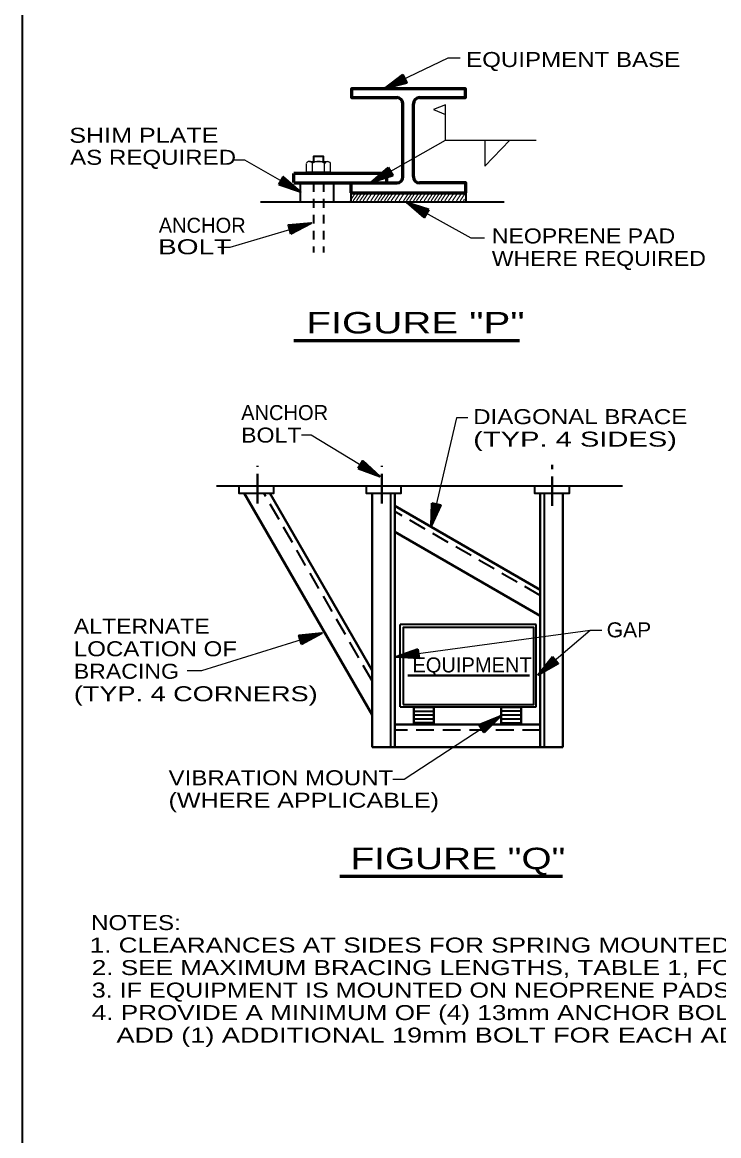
# Model space of a CAD drawing. Extents: x 55 to 190, y 198 to 264.
# Drawn here: x 102.59 to 114.38, y 231.1 to 249.95 of the extents above; entities that cross this region are included whole.
import ezdxf
from ezdxf.enums import TextEntityAlignment as Align

# ---------------------------------------------------------------- set-up
doc = ezdxf.new("R2010")
doc.units = 0
doc.header["$LTSCALE"] = 0.1
for name, pattern in [('DOT_DASHED', [7.7, 5, -1.2, 0.3, -1.2]), ('MEDIUM_DASHED', [4.5, 3, -1.5]), ('SHORT_DASHED', [2.7, 1.5, -1.2])]:
    doc.linetypes.add(name, pattern=pattern)
doc.layers.add('2', color=7, linetype='Continuous', lineweight=40)

msp = doc.modelspace()

# ---------------------------------------------------------------- linework, layer by layer
at = {"layer": '2', "lineweight": 35}
for p, q in [((102.5927, 256.6525), (102.5927, 199.6512)), ((107.3036, 246.9117), (107.3036, 247.2313)), ((107.8661, 246.9117), (107.8661, 247.2313)), ((108.1611, 246.9117), (108.1611, 247.0614)), ((110.0981, 247.0614), (110.0981, 246.9117)), ((106.6236, 246.9117), (110.7471, 246.9117)), ((105.8809, 242.1031), (112.7513, 242.1031)), ((108.8252, 241.9754), (108.8252, 237.6753)), ((111.4329, 237.6753), (111.4329, 241.9754)), ((111.2914, 239.7555), (108.9903, 239.7555)), ((108.9903, 238.3609), (108.9903, 239.7555)), ((111.2914, 238.3609), (111.2914, 239.7555)), ((108.9903, 238.3609), (111.2914, 238.3609)), ((109.5597, 238.3474), (109.2207, 238.3474)), ((111.0397, 238.3498), (110.7011, 238.3498)), ((109.5597, 238.2823), (109.221, 238.2823)), ((109.5594, 238.2164), (109.221, 238.2164)), ((109.5597, 238.1513), (109.221, 238.1513)), ((111.0395, 238.2185), (110.7008, 238.2185)), ((111.0397, 238.2847), (110.7011, 238.2847)), ((110.7011, 238.1537), (111.0397, 238.1537)), ((109.5597, 238.0862), (109.221, 238.0862)), ((110.7008, 238.0876), (111.0395, 238.0876))]:
    msp.add_line(p, q, dxfattribs=at)
at = {"layer": '2'}
for p, q in [((108.7236, 248.8307), (109.044, 249.0471)), ((108.7236, 248.8307), (109.0538, 249.0281)), ((108.7236, 248.8307), (109.0604, 249.0125)), ((109.0686, 248.9966), (108.7236, 248.8307)), ((108.7236, 248.8307), (109.0765, 248.9791)), ((108.7236, 248.8307), (109.0927, 248.9455)), ((108.4929, 247.2371), (108.7979, 247.4747)), ((108.4929, 247.2371), (108.8088, 247.4562)), ((108.4929, 247.2371), (108.8167, 247.4411)), ((108.8257, 247.4258), (108.4929, 247.2371)), ((108.4929, 247.2371), (108.835, 247.4088)), ((108.4929, 247.2371), (108.8532, 247.3766)), ((107.3041, 247.0792), (106.944, 247.2197)), ((107.3041, 247.0792), (106.9541, 247.2384)), ((107.3041, 247.0792), (106.9631, 247.253)), ((106.9715, 247.2686), (107.3041, 247.0792)), ((107.3041, 247.0792), (106.9813, 247.285)), ((107.3041, 247.0792), (106.9998, 247.3175)), ((109.4358, 246.7127), (109.1012, 246.8979)), ((109.1012, 246.8979), (109.4531, 246.7429)), ((109.1012, 246.8979), (109.4083, 246.6632)), ((109.1012, 246.8979), (109.4263, 246.696)), ((109.1012, 246.8979), (109.4443, 246.7283)), ((109.1012, 246.8979), (109.4631, 246.7619)), ((107.4853, 246.5508), (107.1028, 246.4958)), ((107.4853, 246.5508), (107.1133, 246.4598)), ((107.1186, 246.4415), (107.4853, 246.5508)), ((107.4853, 246.5508), (107.1239, 246.4243)), ((107.4853, 246.5508), (107.1282, 246.4079)), ((107.4853, 246.5508), (107.1348, 246.3875)), ((108.3164, 242.4579), (108.6437, 242.2598)), ((108.6437, 242.2598), (108.3265, 242.4741)), ((108.6437, 242.2598), (108.3458, 242.5061)), ((108.6437, 242.2598), (108.2873, 242.4098)), ((108.6437, 242.2598), (108.2979, 242.4283)), ((108.6437, 242.2598), (108.3071, 242.4426)), ((108.5156, 238.2257), (106.3508, 241.9754)), ((108.5138, 238.9774), (106.7829, 241.9754)), ((108.5138, 237.6753), (108.5138, 241.9754)), ((108.8974, 237.6753), (108.8974, 241.9754)), ((111.361, 241.9754), (111.361, 237.6753)), ((111.7446, 241.9754), (111.7446, 237.6753)), ((111.361, 240.3421), (108.8974, 241.7645)), ((109.5136, 241.4173), (109.5451, 241.8026)), ((109.5136, 241.4173), (109.566, 241.7983)), ((109.5136, 241.4173), (109.5824, 241.7938)), ((109.5999, 241.7901), (109.5136, 241.4173)), ((109.5136, 241.4173), (109.6187, 241.7856)), ((109.5136, 241.4173), (109.6549, 241.7772)), ((111.361, 239.8992), (108.8974, 241.3216)), ((107.6631, 239.6084), (107.2814, 239.5475)), ((107.6631, 239.6084), (107.2927, 239.5121)), ((107.298, 239.4936), (107.6631, 239.6084)), ((107.6631, 239.6084), (107.3036, 239.4766)), ((107.6631, 239.6084), (107.3083, 239.4602)), ((107.6631, 239.6084), (107.3152, 239.4401)), ((108.9196, 239.2078), (109.2911, 239.315)), ((108.9196, 239.2078), (109.2946, 239.2938)), ((108.9196, 239.2078), (109.2962, 239.2769)), ((109.2988, 239.2594), (108.9196, 239.2078)), ((108.9196, 239.2078), (109.3012, 239.2404)), ((108.9196, 239.2078), (109.3062, 239.2033)), ((111.3226, 238.9041), (111.5782, 239.1941)), ((111.3226, 238.9041), (111.5925, 239.1779)), ((111.3226, 238.9041), (111.603, 239.1647)), ((111.6147, 239.1512), (111.3226, 238.9041)), ((111.3226, 238.9041), (111.6269, 239.1364)), ((111.3226, 238.9041), (111.6509, 239.1078)), ((109.1194, 238.8877), (111.1771, 238.8877)), ((109.221, 238.0598), (109.221, 238.3614)), ((109.5597, 238.3614), (109.5597, 238.0624)), ((110.7011, 238.0598), (110.7011, 238.3614)), ((111.0397, 238.3614), (111.0397, 238.0624)), ((110.6873, 238.1997), (110.3365, 238.0376)), ((110.6873, 238.1997), (110.3569, 238.0063)), ((110.3672, 237.9902), (110.6873, 238.1997)), ((110.6873, 238.1997), (110.3772, 237.9754)), ((110.6873, 238.1997), (110.386, 237.9608)), ((110.6873, 238.1997), (110.3981, 237.9431)), ((111.361, 238.0587), (108.8974, 238.0587)), ((111.7446, 237.6753), (108.5138, 237.6753))]:
    msp.add_line(p, q, dxfattribs=at)
at = {"layer": '2', "lineweight": 60}
for p, q in [((109.0363, 247.3371), (109.0363, 248.569)), ((109.2125, 247.3371), (109.2125, 248.569)), ((107.1864, 247.2379), (107.1864, 247.3924)), ((107.1864, 247.2313), (108.9305, 247.2313)), ((108.1611, 247.0614), (108.1611, 247.2313)), ((108.1611, 247.0614), (110.0981, 247.0614)), ((107.1898, 244.5611), (111.0109, 244.5611)), ((107.9669, 235.4902), (111.7369, 235.4902))]:
    msp.add_line(p, q, dxfattribs=at)
at = {"layer": '2', "lineweight": 25}
for p, q in [((107.4017, 247.4194), (107.4017, 247.562)), ((107.4533, 247.593), (107.7597, 247.593)), ((107.5033, 247.4194), (107.5033, 247.562)), ((107.7089, 247.4194), (107.7089, 247.562)), ((107.811, 247.4194), (107.811, 247.5607)), ((107.4017, 247.4194), (107.811, 247.4194)), ((112.2066, 239.6497), (108.9196, 239.2078))]:
    msp.add_line(p, q, dxfattribs=at)
at = {"layer": '2', "linetype": 'SHORT_DASHED', "lineweight": 35}
for p, q in [((107.5227, 247.2313), (107.5227, 246.0526)), ((107.6907, 247.2313), (107.6907, 246.0526))]:
    msp.add_line(p, q, dxfattribs=at)
at = {"layer": '2', "lineweight": 13}
for p, q in [((108.1402, 246.9291), (108.2206, 247.0464)), ((108.1822, 246.9903), (108.2206, 247.0464)), ((108.195, 246.9291), (108.2754, 247.0464)), ((108.195, 246.9291), (108.2754, 247.0464)), ((108.25, 246.9291), (108.3304, 247.0464)), ((108.25, 246.9291), (108.3304, 247.0464)), ((108.3085, 246.9291), (108.3889, 247.0464)), ((108.3085, 246.9291), (108.3889, 247.0464)), ((108.3632, 246.9291), (108.4437, 247.0464)), ((108.3632, 246.9291), (108.4437, 247.0464)), ((108.4254, 246.9291), (108.5058, 247.0464)), ((108.4254, 246.9291), (108.5058, 247.0464)), ((108.4913, 246.9291), (108.5717, 247.0464)), ((108.4913, 246.9291), (108.5717, 247.0464)), ((108.5537, 246.9291), (108.6342, 247.0464)), ((108.6085, 246.9291), (108.6889, 247.0464)), ((108.6635, 246.9291), (108.744, 247.0464)), ((108.722, 246.9291), (108.8024, 247.0464)), ((108.7768, 246.9291), (108.8572, 247.0464)), ((108.839, 246.9291), (108.9194, 247.0464)), ((108.9048, 246.9291), (108.9853, 247.0464)), ((108.9707, 246.9291), (109.0511, 247.0464)), ((109.044, 246.9291), (109.1244, 247.0464)), ((109.0988, 246.9291), (109.1792, 247.0464)), ((109.1538, 246.9291), (109.2342, 247.0464)), ((109.2123, 246.9291), (109.2927, 247.0464)), ((109.267, 246.9291), (109.3475, 247.0464)), ((109.3292, 246.9291), (109.4097, 247.0464)), ((109.3951, 246.9291), (109.4755, 247.0464)), ((109.4575, 246.9291), (109.538, 247.0464)), ((109.5123, 246.9291), (109.5927, 247.0464)), ((109.5674, 246.9291), (109.6478, 247.0464)), ((109.6258, 246.9291), (109.7063, 247.0464)), ((109.6806, 246.9291), (109.761, 247.0464)), ((109.7428, 246.9291), (109.8232, 247.0464)), ((109.8087, 246.9291), (109.8891, 247.0464)), ((109.8745, 246.9291), (109.955, 247.0464)), ((109.9404, 246.9291), (110.0208, 247.0464)), ((110.0026, 246.9291), (110.083, 247.0464)), ((110.0611, 246.9291), (110.0777, 246.9532))]:
    msp.add_line(p, q, dxfattribs=at)
at = {"layer": '2', "linetype": 'DOT_DASHED'}
for p, q in [((111.562, 241.7624), (111.562, 242.459)), ((106.5715, 241.8036), (106.5715, 242.441)), ((108.6762, 241.8036), (108.6762, 242.441))]:
    msp.add_line(p, q, dxfattribs=at)
at = {"layer": '2', "linetype": 'MEDIUM_DASHED', "lineweight": 35}
for p, q in [((108.5138, 238.8022), (106.6818, 241.9754)), ((111.361, 240.2444), (108.8974, 241.6668)), ((111.361, 237.9645), (108.8974, 237.9645))]:
    msp.add_line(p, q, dxfattribs=at)
at = {"layer": '2', "lineweight": 25}
for points in [[(110.0071, 249.3443), (109.7957, 249.3443), (108.7236, 248.8307)], [(109.7586, 247.952), (109.7586, 248.5502), (109.5531, 248.4754), (109.7586, 248.3912)], [(108.4929, 247.2371), (109.7586, 247.952), (111.2914, 247.952)], [(110.4222, 247.952), (110.4222, 247.5128), (110.8426, 247.952)], [(106.1566, 247.6229), (106.3529, 247.6229), (107.3041, 247.0792)], [(110.4148, 246.2941), (110.1883, 246.2941), (109.1012, 246.8979)], [(105.9, 246.1431), (106.1114, 246.1431), (107.4853, 246.5508)], [(110.1351, 243.2541), (109.9417, 243.2541), (109.5136, 241.4173)], [(107.3179, 242.9641), (107.4835, 242.9641), (108.6437, 242.2598)], [(112.3997, 239.6497), (112.2066, 239.6497), (111.3226, 238.9041)], [(105.3846, 238.9731), (105.633, 238.9731), (107.6631, 239.6084)], [(108.8646, 237.1364), (109.0578, 237.1364), (110.6873, 238.1997)]]:
    msp.add_lwpolyline(points, dxfattribs=at)
at = {"layer": '2'}
for points in [[(109.0355, 249.0646), (109.1014, 248.9265), (108.7236, 248.8307)], [(109.0355, 249.0646), (108.7236, 248.8307), (109.085, 248.9622)], [(108.7884, 247.4916), (108.8633, 247.358), (108.4929, 247.2371)], [(108.7884, 247.4916), (108.4929, 247.2371), (108.8445, 247.3927)], [(106.9342, 247.2027), (107.0104, 247.3355), (107.3041, 247.0792)], [(106.9342, 247.2027), (107.3041, 247.0792), (106.9906, 247.3017)], [(109.4724, 246.7789), (109.398, 246.6452), (109.1012, 246.8979)], [(109.4724, 246.7789), (109.1012, 246.8979), (109.4173, 246.6794)], [(107.1403, 246.369), (107.0972, 246.5156), (107.4853, 246.5508)], [(107.1403, 246.369), (107.4853, 246.5508), (107.1078, 246.478)], [(108.2772, 242.3931), (108.3569, 242.5238), (108.6437, 242.2598)], [(108.2772, 242.3931), (108.6437, 242.2598), (108.336, 242.4905)], [(109.5261, 241.8071), (109.6753, 241.7722), (109.5136, 241.4173)], [(109.5261, 241.8071), (109.5136, 241.4173), (109.6372, 241.7814)], [(107.321, 239.4213), (107.2755, 239.5676), (107.6631, 239.6084)], [(107.321, 239.4213), (107.6631, 239.6084), (107.2866, 239.5301)], [(109.2885, 239.3343), (109.3086, 239.1827), (108.9196, 239.2078)], [(109.2885, 239.3343), (108.9196, 239.2078), (109.3038, 239.2216)], [(111.5657, 239.2089), (111.6642, 239.0917), (111.3226, 238.9041)], [(111.5657, 239.2089), (111.3226, 238.9041), (111.6393, 239.1221)], [(110.4087, 237.927), (110.3254, 238.0553), (110.6873, 238.1997)], [(110.4087, 237.927), (110.6873, 238.1997), (110.3463, 238.0222)]]:
    msp.add_lwpolyline(points, dxfattribs=at)
at = {"layer": '2', "lineweight": 60}
for points in [[(109.3184, 248.6749), (110.0965, 248.6749), (110.0965, 248.8262), (108.1632, 248.8262), (108.1632, 248.6749), (108.9305, 248.6749)], [(108.7633, 247.2379), (108.7633, 247.3924), (107.1864, 247.3924)], [(110.0981, 247.0614), (110.0981, 247.2313), (109.3184, 247.2313)]]:
    msp.add_lwpolyline(points, dxfattribs=at)
at = {"layer": '2', "lineweight": 35}
for points in [[(107.6907, 247.5938), (107.6907, 247.6798), (107.5227, 247.6798), (107.5227, 247.5938)], [(106.2593, 242.1031), (106.2593, 241.9754), (106.8519, 241.9754), (106.8519, 242.1031)], [(108.4135, 242.1031), (108.4135, 241.9754), (109.0062, 241.9754), (109.0062, 242.1031)], [(111.2652, 242.1031), (111.2652, 241.9754), (111.8578, 241.9754), (111.8578, 242.1031)]]:
    msp.add_lwpolyline(points, dxfattribs=at)
msp.add_lwpolyline([(109.0422, 238.3992), (111.2527, 238.3992), (111.2527, 239.7026), (109.0422, 239.7026)], close=True, dxfattribs=at)
at = {"layer": '2', "lineweight": 60}
for centre, start, end in [((108.9305, 248.569), 0, 90), ((109.3184, 248.569), 90, 180), ((108.9305, 247.3371), 270, 0), ((109.3184, 247.3371), 180, 270)]:
    msp.add_arc(centre, 0.1058, start, end, dxfattribs=at)
at = {"layer": '2', "lineweight": 25}
for centre, radius, start, end in [((107.4526, 247.5357), 0.0572, 27.8877, 152.03419), ((107.606, 247.4038), 0.189, 57.00616, 122.94297), ((107.7595, 247.5352), 0.0572, 26.78269, 151.8391)]:
    msp.add_arc(centre, radius, start, end, dxfattribs=at)

# ---------------------------------------------------------------- texts
at = {"layer": '2'}
for s, width, p in [('EQUIPMENT BASE', 1.2, (110.106, 249.1932)), ('SHIM PLATE', 1.25, (103.3888, 247.9102)), ('AS REQUIRED', 1.2, (103.4026, 247.5374)), ('NEOPRENE PAD', 1.15, (110.54, 246.206)), ('WHERE REQUIRED', 1.15, (110.54, 245.825)), ('DIAGONAL BRACE', 1.2, (110.2251, 243.1461)), ('BOLT', 1.15, (106.2974, 242.8339)), ('(TYP. 4 SIDES)', 1.45, (110.2251, 242.7651)), ('ALTERNATE', 1.15, (103.465, 239.597)), ('GAP', 1.05, (112.4846, 239.5364)), ('LOCATION OF', 1.2, (103.465, 239.216)), ('BRACING', 1.15, (103.465, 238.835)), ('(TYP. 4 CORNERS)', 1.35, (103.465, 238.454)), ('VIBRATION MOUNT', 1.2, (105.0686, 237.0319)), ('(WHERE APPLICABLE)', 1.25, (105.0686, 236.6509)), ('NOTES:', 1.2, (103.7573, 234.5793)), ('1. CLEARANCES AT SIDES FOR SPRING MOUNTED EQUIPMENT AS IN FIG. "R" & "S", SHALL BE IN ACCORDANCE WITH MFR\'S. RECOMMENDATIONS.', 1.3, (103.733, 234.1984)), ('2. SEE MAXIMUM BRACING LENGTHS, TABLE 1, FOR BRACE SIZES.', 1.3, (103.7692, 233.8174)), ('3. IF EQUIPMENT IS MOUNTED ON NEOPRENE PADS, ANCHOR BOLTS SHALL BE ISOLATED FROM EQUIPMENT BY A NEOPRENE SLEEVE AND WASHER.', 1.25, (103.7692, 233.4363)), ('4. PROVIDE A MINIMUM OF (4) 13mm ANCHOR BOLTS FOR EQUIPMENT UP TO 4,500 Kg AND (4) 19mm BOLTS FOR EQUIPMENT WEIGHT OF 4,500Kg OR GREATER.', 1.3, (103.7692, 233.0554)), ('   ADD (1) ADDITIONAL 19mm BOLT FOR EACH ADDITIONAL 1,135Kg OF EQUIPMENT WEIGHT.', 1.35, (103.8058, 232.6744))]:
    msp.add_text(s, height=0.254, dxfattribs=dict(at, width=width)).set_placement(p)
msp.add_text('ANCHOR', height=0.254, dxfattribs=at).set_placement((106.3741, 246.3859), align=Align.RIGHT)
at = {"layer": '2', "width": 1.4}
msp.add_text('BOLT  ', height=0.254, dxfattribs=at).set_placement((106.3953, 246.0224), align=Align.RIGHT)
at = {"layer": '2'}
for s, width, p in [('FIGURE "P"', 1.4, (109.2476, 244.6815)), ('FIGURE "Q"', 1.35, (109.9668, 235.6103))]:
    msp.add_text(s, height=0.3633, dxfattribs=dict(at, width=width)).set_placement(p, align=Align.CENTER)
msp.add_text('ANCHOR', height=0.254, dxfattribs=at).set_placement((106.2974, 243.2149))
msp.add_text('EQUIPMENT', height=0.254, dxfattribs=at).set_placement((110.206, 238.9422), align=Align.CENTER)

doc.saveas('drawing.dxf')
